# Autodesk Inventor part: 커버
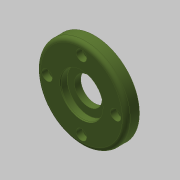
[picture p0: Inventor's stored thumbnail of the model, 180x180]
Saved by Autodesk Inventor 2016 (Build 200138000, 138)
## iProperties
Created: 2016-06
Part Number: 커버
Material: 알루미늄 6061
Document SubType Name: Modeling
Designer: mduedu
Density: 2.71 g/cm^3
Appearance: 올리브 녹색
Author: mduedu
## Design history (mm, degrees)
sketch "스케치1"
  geometry: C1 r 34 at (0, 0); 1 further point
  constraints: 1 centre point, 1 coincident
  dimensions: "d0" = 68 diameter of C1
extrude "돌출1" new body sketch "스케치1" distance "d2" = 10; taper "d3" = 0 deg
sketch "스케치2"
  geometry: C1 r 21 at (0, 0); 1 further point
  constraints: 1 centre point, 1 coincident
  dimensions: "d4" = 42 diameter of C1
extrude "돌출2" join sketch "스케치2" distance "d6" = 3; taper "d7" = 0 deg
fillet "모깎기1" dims "d8" = 3
hole "구멍1" diameter "d11" = 35; stored, may be unused: countersink angle "d15" = 90 deg, drill point angle "d17" = 0 deg; dims "d9" = 10, "d10" = 10, "d12" = 6, "d13" = 4, "d14" = 2, "d16" = 3
hole "구멍2" diameter "d20" = 32; stored, may be unused: countersink angle "d24" = 90 deg, drill point angle "d26" = 0 deg; dims "d21" = 6, "d22" = 4, "d23" = 2, "d25" = 5.2, "d46" = 10, "d47" = 10
hole "구멍3" diameter "d29" = 21; stored, may be unused: countersink angle "d33" = 90 deg, drill point angle "d35" = 0 deg; dims "d27" = 10, "d28" = 10, "d30" = 6, "d31" = 4, "d32" = 2, "d34" = 5
fillet "모깎기2" dims "d36" = 3
fillet "모깎기3" dims "d37" = 0.1
chamfer "모따기1" distance "d38" = 0.75; stored, may be unused: second distance "d39" = 2, angle "d40" = 30 deg
chamfer "모따기2" distance "d42" = 0.5; stored, may be unused: second distance "d43" = 2, angle "d44" = 30 deg
sketch "스케치3" dims "d48" = 52
  geometry: 6 further points
  constraints: 2 vertical alignment, 1 coincident, 7 other
  dimensions: "d51" = 360 deg dimension on point (0, 0) point (0, 26) (derived)
sketch "스케치4"
  geometry: 4 further points
hole "구멍4" sketch "스케치4" at (0, 26), (-26, 0), (0, -26), (26, 0) diameter "d53" = 4.5; stored, may be unused: countersink angle "d57" = 90 deg, drill point angle "d59" = 0 deg; dims "d54" = 6, "d55" = 8, "d56" = 4.6, "d58" = 8
node "솔리드1"
